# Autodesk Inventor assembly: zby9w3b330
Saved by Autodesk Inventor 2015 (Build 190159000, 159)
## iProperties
Created: 2019-08
Part Number: zby9w3b330
Checked By: TraceParts S.A.
Catalog Web Link: www.traceparts.com
Document SubType Name: Assembly
Designer: TraceParts
Company: TraceParts S.A.
Author: TraceParts
DESIGN: ILL. RING 24V 2 WHITE/RED FIXED LED TEXT EMERGENCY STOP WITH LOGO YELLOW LABEL
REFERENCE: ZBY9W3B330
SUPPLIER: Schneider Electric
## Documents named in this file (3)
- C:\Program Files (x86)\Trace Software\PartsXML Tools\RobotPartsAuto\SCHNEIDER_ELECTRIC\CAD\Temp\zby9w3b330.iam
- C:\Program Files (x86)\Trace Software\PartsXML Tools\RobotPartsAuto\SCHNEIDER_ELECTRIC\CAD\Temp\zby9w3b330_01.ipt
- C:\Program Files (x86)\Trace Software\PartsXML Tools\RobotPartsAuto\SCHNEIDER_ELECTRIC\CAD\Temp\zby9w3b330_02.ipt
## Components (2 placed, 2 different names)
1. zby9w3b330_01:1
2. zby9w3b330_02:1
